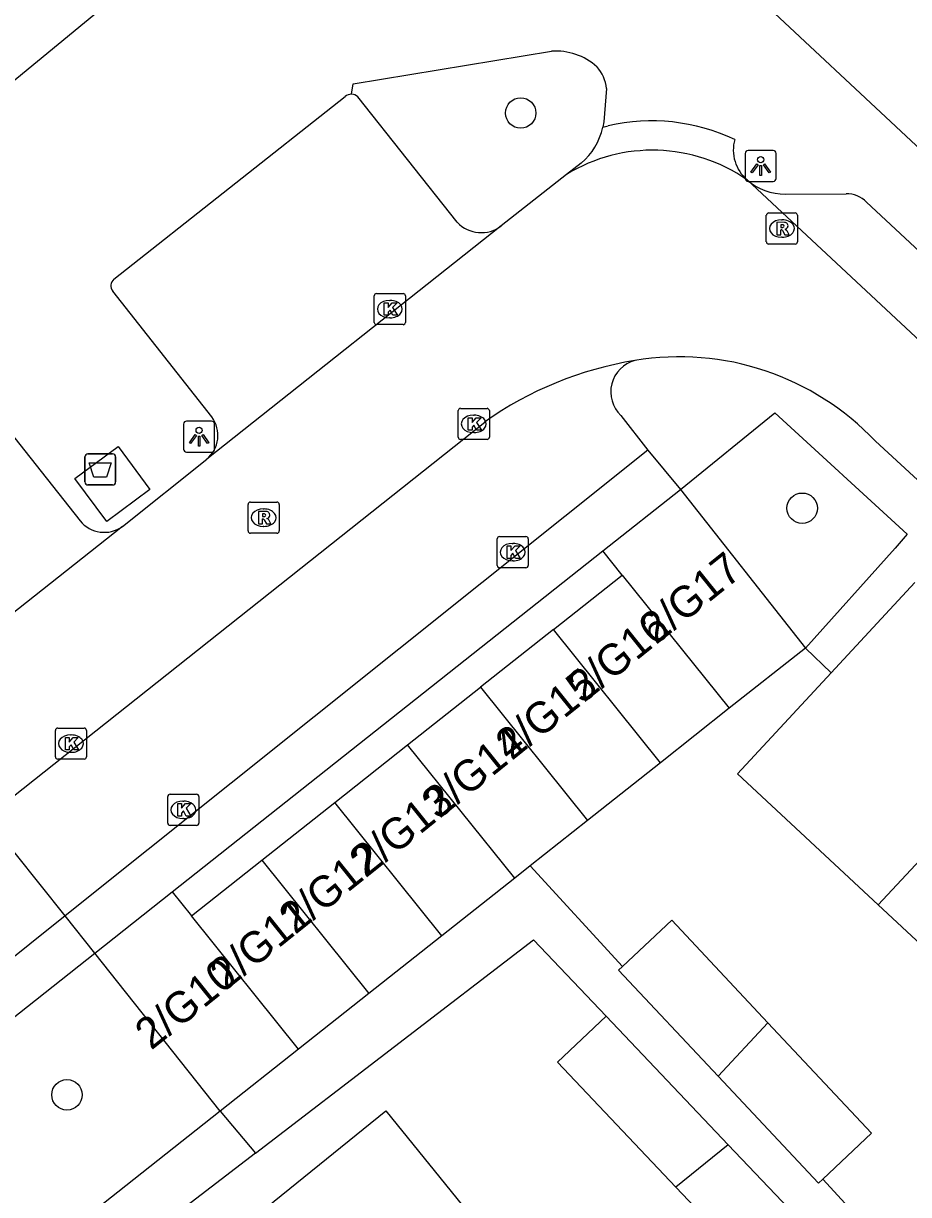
# Model space of a CAD drawing. Extents: x 162347 to 162868, y 381221 to 381813.
# Drawn here: x 162519.02 to 162547.46, y 381682.17 to 381719.8 of the extents above; entities that cross this region are included whole.
import ezdxf

# ---------------------------------------------------------------- set-up
doc = ezdxf.new("R2010")
doc.units = 0
for name, color, linetype in [('IMGEO_Afval_apart_plaats', 7, 'Continuous'), ('IMGEO_Boom', 7, 'Continuous'), ('IMGEO_Kolk', 7, 'Continuous'), ('IMGEO_Lichtpunt', 7, 'Continuous'), ('IMGEO_Pand', 7, 'Continuous'), ('IMGEO_Pand_nummerreeks', 7, 'Continuous'), ('IMGEO_Parkeervlak_open', 7, 'Continuous'), ('IMGEO_Rijbaan_lokaal_open', 7, 'Continuous'), ('IMGEO_Rioolput', 7, 'Continuous'), ('IMGEO_Voetpad_gesloten', 7, 'Continuous'), ('IMGEO_Voetpad_open', 7, 'Continuous')]:
    doc.layers.add(name, color=color, linetype=linetype)

msp = doc.modelspace()

# ---------------------------------------------------------------- linework, layer by layer
at = {"layer": 'IMGEO_Afval_apart_plaats'}
for p, q in [((162520.994, 381705.07), (162520.994, 381705.87)), ((162520.994, 381705.87), (162520.994, 381705.07)), ((162521.094, 381705.97), (162521.884, 381705.97)), ((162521.884, 381705.97), (162521.094, 381705.97)), ((162521.984, 381705.87), (162521.984, 381705.07)), ((162521.984, 381705.07), (162521.984, 381705.87)), ((162521.884, 381704.97), (162521.094, 381704.97)), ((162521.094, 381704.97), (162521.884, 381704.97))]:
    msp.add_line(p, q, dxfattribs=at)
msp.add_lwpolyline([(162521.137, 381705.684), (162521.841, 381705.684), (162521.692, 381705.214), (162521.286, 381705.214), (162521.137, 381705.684)], dxfattribs=at)
for centre, start, end in [((162521.094, 381705.87), 90, 180), ((162521.094, 381705.87), 90, 180), ((162521.884, 381705.87), 0, 90), ((162521.884, 381705.87), 360, 90), ((162521.094, 381705.07), 180, 270), ((162521.094, 381705.07), 180, 270), ((162521.884, 381705.07), 270, 0), ((162521.884, 381705.07), 270, 0)]:
    msp.add_arc(centre, 0.1, start, end, dxfattribs=at)
at = {"layer": 'IMGEO_Boom'}
for centre in [(162535, 381716.921), (162544.045, 381704.221), (162520.419, 381685.371)]:
    msp.add_circle(centre, 0.489, dxfattribs=at)
at = {"layer": 'IMGEO_Kolk'}
for p, q in [((162530.293, 381710.194), (162530.293, 381711.046)), ((162530.368, 381711.12), (162531.22, 381711.12)), ((162530.781, 381710.9), (162530.806, 381710.9)), ((162531.294, 381711.046), (162531.294, 381710.194)), ((162530.804, 381710.34), (162530.779, 381710.34)), ((162531.22, 381710.12), (162530.368, 381710.12)), ((162532.991, 381706.505), (162532.991, 381707.357)), ((162533.066, 381707.431), (162533.918, 381707.431)), ((162533.479, 381707.211), (162533.504, 381707.211)), ((162533.992, 381707.357), (162533.992, 381706.505)), ((162533.918, 381706.431), (162533.066, 381706.431)), ((162533.502, 381706.651), (162533.477, 381706.651)), ((162534.243, 381702.384), (162534.243, 381703.236)), ((162534.318, 381703.31), (162535.17, 381703.31)), ((162534.731, 381703.09), (162534.756, 381703.09)), ((162535.244, 381703.236), (162535.244, 381702.384)), ((162535.17, 381702.31), (162534.318, 381702.31)), ((162534.754, 381702.53), (162534.729, 381702.53)), ((162520.046, 381696.231), (162520.046, 381697.083)), ((162520.121, 381697.157), (162520.973, 381697.157)), ((162521.047, 381697.083), (162521.047, 381696.231)), ((162520.534, 381696.937), (162520.559, 381696.937)), ((162520.557, 381696.377), (162520.532, 381696.377)), ((162520.973, 381696.157), (162520.121, 381696.157)), ((162523.658, 381694.103), (162523.658, 381694.955)), ((162523.733, 381695.029), (162524.585, 381695.029)), ((162524.146, 381694.809), (162524.171, 381694.809)), ((162524.659, 381694.955), (162524.659, 381694.103)), ((162524.585, 381694.029), (162523.733, 381694.029)), ((162524.169, 381694.249), (162524.144, 381694.249))]:
    msp.add_line(p, q, dxfattribs=at)
for points in [[(162530.293, 381710.194), (162530.293, 381711.046)], [(162530.368, 381711.12), (162531.22, 381711.12)], [(162531.294, 381711.046), (162531.294, 381710.194)], [(162530.614, 381710.82), (162530.737, 381710.82), (162530.737, 381710.669), (162530.867, 381710.82), (162531.031, 381710.82), (162530.885, 381710.669), (162531.038, 381710.42), (162530.886, 381710.42), (162530.801, 381710.584), (162530.737, 381710.517), (162530.737, 381710.42), (162530.614, 381710.42), (162530.614, 381710.82)], [(162531.22, 381710.12), (162530.368, 381710.12)], [(162532.991, 381706.505), (162532.991, 381707.357)], [(162533.066, 381707.431), (162533.918, 381707.431)], [(162533.312, 381707.131), (162533.435, 381707.131), (162533.435, 381706.98), (162533.565, 381707.131), (162533.729, 381707.131), (162533.583, 381706.98), (162533.736, 381706.731), (162533.584, 381706.731), (162533.499, 381706.895), (162533.435, 381706.828), (162533.435, 381706.731), (162533.312, 381706.731), (162533.312, 381707.131)], [(162533.992, 381707.357), (162533.992, 381706.505)], [(162533.918, 381706.431), (162533.066, 381706.431)], [(162534.243, 381702.384), (162534.243, 381703.236)], [(162534.318, 381703.31), (162535.17, 381703.31)], [(162534.564, 381703.01), (162534.687, 381703.01), (162534.687, 381702.859), (162534.817, 381703.01), (162534.981, 381703.01), (162534.835, 381702.859), (162534.988, 381702.61), (162534.836, 381702.61), (162534.751, 381702.774), (162534.687, 381702.707), (162534.687, 381702.61), (162534.564, 381702.61), (162534.564, 381703.01)], [(162535.244, 381703.236), (162535.244, 381702.384)], [(162535.17, 381702.31), (162534.318, 381702.31)], [(162520.046, 381696.231), (162520.046, 381697.083)], [(162520.121, 381697.157), (162520.973, 381697.157)], [(162521.047, 381697.083), (162521.047, 381696.231)], [(162520.367, 381696.857), (162520.49, 381696.857), (162520.49, 381696.706), (162520.62, 381696.857), (162520.784, 381696.857), (162520.638, 381696.706), (162520.791, 381696.457), (162520.639, 381696.457), (162520.554, 381696.621), (162520.49, 381696.554), (162520.49, 381696.457), (162520.367, 381696.457), (162520.367, 381696.857)], [(162520.973, 381696.157), (162520.121, 381696.157)], [(162523.658, 381694.103), (162523.658, 381694.955)], [(162523.733, 381695.029), (162524.585, 381695.029)], [(162523.979, 381694.729), (162524.102, 381694.729), (162524.102, 381694.578), (162524.232, 381694.729), (162524.396, 381694.729), (162524.25, 381694.578), (162524.403, 381694.329), (162524.251, 381694.329), (162524.166, 381694.493), (162524.102, 381694.426), (162524.102, 381694.329), (162523.979, 381694.329), (162523.979, 381694.729)], [(162524.659, 381694.955), (162524.659, 381694.103)], [(162524.585, 381694.029), (162523.733, 381694.029)]]:
    msp.add_lwpolyline(points, dxfattribs=at)
for centre, start, end in [((162530.37, 381711.044), 91.552, 178.448), ((162530.37, 381711.044), 91.552, 178.448), ((162531.218, 381711.044), 1.552, 88.448), ((162531.218, 381711.044), 1.552, 88.448), ((162530.37, 381710.196), 181.552, 268.448), ((162530.37, 381710.196), 181.552, 268.448), ((162531.218, 381710.196), 271.552, 358.448), ((162531.218, 381710.196), 271.552, 358.448), ((162533.068, 381707.355), 91.552, 178.448), ((162533.068, 381707.355), 91.552, 178.448), ((162533.916, 381707.355), 1.552, 88.448), ((162533.916, 381707.355), 1.552, 88.448), ((162533.068, 381706.507), 181.552, 268.448), ((162533.068, 381706.507), 181.552, 268.448), ((162533.916, 381706.507), 271.552, 358.448), ((162533.916, 381706.507), 271.552, 358.448), ((162534.32, 381703.234), 91.552, 178.448), ((162534.32, 381703.234), 91.552, 178.448), ((162535.168, 381703.234), 1.552, 88.448), ((162535.168, 381703.234), 1.552, 88.448), ((162534.32, 381702.386), 181.552, 268.448), ((162534.32, 381702.386), 181.552, 268.448), ((162535.168, 381702.386), 271.552, 358.448), ((162535.168, 381702.386), 271.552, 358.448), ((162520.123, 381697.081), 91.552, 178.448), ((162520.123, 381697.081), 91.552, 178.448), ((162520.971, 381697.081), 1.552, 88.448), ((162520.971, 381697.081), 1.552, 88.448), ((162520.123, 381696.233), 181.552, 268.448), ((162520.123, 381696.233), 181.552, 268.448), ((162520.971, 381696.233), 271.552, 358.448), ((162520.971, 381696.233), 271.552, 358.448), ((162523.735, 381694.953), 91.552, 178.448), ((162523.735, 381694.953), 91.552, 178.448), ((162524.583, 381694.953), 1.552, 88.448), ((162524.583, 381694.953), 1.552, 88.448), ((162523.735, 381694.105), 181.552, 268.448), ((162523.735, 381694.105), 181.552, 268.448), ((162524.583, 381694.105), 271.552, 358.448), ((162524.583, 381694.105), 271.552, 358.448)]:
    msp.add_arc(centre, 0.0765, start, end, dxfattribs=at)
for centre, major_axis, ratio, start_param, end_param in [((162530.78, 381710.62), (-0.387, 0.002), 0.722429, 4.712389, 7.853982), ((162530.805, 381710.62), (-0.39, 0.002), 0.717154, 1.570796, 4.712389), ((162533.478, 381706.931), (-0.387, 0.002), 0.722429, 4.712389, 7.853982), ((162533.503, 381706.931), (-0.39, 0.002), 0.717154, 1.570796, 4.712389), ((162534.73, 381702.81), (-0.387, 0.002), 0.722429, 4.712389, 7.853982), ((162534.755, 381702.81), (-0.39, 0.002), 0.717154, 1.570796, 4.712389), ((162520.533, 381696.657), (-0.387, 0.002), 0.722429, 4.712389, 7.853982), ((162520.558, 381696.657), (-0.39, 0.002), 0.717154, 1.570796, 4.712389), ((162524.145, 381694.529), (-0.387, 0.002), 0.722429, 4.712389, 7.853982), ((162524.17, 381694.529), (-0.39, 0.002), 0.717154, 1.570796, 4.712389)]:
    msp.add_ellipse(centre, major_axis=major_axis, ratio=ratio, start_param=start_param, end_param=end_param, dxfattribs=at)
at = {"layer": 'IMGEO_Lichtpunt'}
for p, q in [((162542.213, 381715.623), (162542.213, 381714.816)), ((162542.213, 381715.623), (162542.213, 381714.816)), ((162543.115, 381715.718), (162542.307, 381715.718)), ((162543.115, 381715.718), (162542.307, 381715.718)), ((162543.209, 381714.816), (162543.209, 381715.623)), ((162543.209, 381714.816), (162543.209, 381715.623)), ((162542.307, 381714.722), (162543.115, 381714.722)), ((162542.307, 381714.722), (162543.115, 381714.722)), ((162524.167, 381706.926), (162524.167, 381706.119)), ((162524.167, 381706.926), (162524.167, 381706.119)), ((162525.069, 381707.021), (162524.261, 381707.021)), ((162525.069, 381707.021), (162524.261, 381707.021)), ((162525.163, 381706.119), (162525.163, 381706.926)), ((162525.163, 381706.119), (162525.163, 381706.926)), ((162524.261, 381706.025), (162525.069, 381706.025)), ((162524.261, 381706.025), (162525.069, 381706.025))]:
    msp.add_line(p, q, dxfattribs=at)
for points in [[(162542.587, 381715.287), (162542.626, 381715.259), (162542.438, 381714.997), (162542.4, 381715.024), (162542.587, 381715.287)], [(162542.689, 381715.239), (162542.736, 381715.239), (162542.736, 381714.917), (162542.689, 381714.917), (162542.689, 381715.239)], [(162542.799, 381715.259), (162542.837, 381715.286), (162543.024, 381715.024), (162542.985, 381714.996), (162542.799, 381715.259)], [(162524.541, 381706.59), (162524.58, 381706.562), (162524.392, 381706.3), (162524.354, 381706.327), (162524.541, 381706.59)], [(162524.643, 381706.542), (162524.69, 381706.542), (162524.69, 381706.22), (162524.643, 381706.22), (162524.643, 381706.542)], [(162524.753, 381706.562), (162524.791, 381706.589), (162524.978, 381706.327), (162524.939, 381706.299), (162524.753, 381706.562)]]:
    msp.add_lwpolyline(points, dxfattribs=at)
for centre in [(162542.712, 381715.421), (162524.666, 381706.724)]:
    msp.add_circle(centre, 0.0994, dxfattribs=at)
for centre, start, end in [((162542.307, 381715.623), 90, 180), ((162542.307, 381715.623), 90, 180), ((162543.115, 381715.623), 0, 90), ((162543.115, 381715.623), 0, 90), ((162542.307, 381714.816), 180, 270), ((162542.307, 381714.816), 180, 270), ((162543.115, 381714.816), 270, 0), ((162543.115, 381714.816), 270, 360), ((162524.261, 381706.926), 90, 180), ((162524.261, 381706.926), 90, 180), ((162525.069, 381706.926), 0, 90), ((162525.069, 381706.926), 0, 90), ((162524.261, 381706.119), 180, 270), ((162524.261, 381706.119), 180, 270), ((162525.069, 381706.119), 270, 0), ((162525.069, 381706.119), 270, 360)]:
    msp.add_arc(centre, 0.0946, start, end, dxfattribs=at)
at = {"layer": 'IMGEO_Pand'}
for points in [[(162518.63, 381717.886), (162525.696, 381723.717)], [(162537.642, 381702.856), (162540.132, 381704.823)], [(162540.132, 381704.823), (162544.148, 381699.726)], [(162538.262, 381702.071), (162537.642, 381702.856)], [(162536.051, 381700.322), (162538.262, 381702.071)], [(162538.262, 381702.071), (162541.703, 381697.791)], [(162544.973, 381698.927), (162547.662, 381701.832)], [(162536.051, 381700.322), (162533.709, 381698.468)], [(162539.492, 381696.043), (162536.051, 381700.322)], [(162544.148, 381699.726), (162541.703, 381697.791)], [(162546.49, 381691.473), (162541.97, 381695.681), (162544.973, 381698.927)], [(162531.366, 381696.615), (162533.709, 381698.468)], [(162533.709, 381698.468), (162537.149, 381694.189)], [(162541.703, 381697.791), (162539.492, 381696.043)], [(162552.208, 381697.599), (162546.49, 381691.473)], [(162529.023, 381694.761), (162531.366, 381696.615)], [(162534.807, 381692.336), (162531.366, 381696.615)], [(162539.492, 381696.043), (162537.149, 381694.189)], [(162526.68, 381692.908), (162529.023, 381694.761)], [(162532.464, 381690.482), (162529.023, 381694.761)], [(162537.149, 381694.189), (162535.306, 381692.731)], [(162524.422, 381691.121), (162526.68, 381692.908)], [(162526.68, 381692.908), (162530.121, 381688.629)], [(162535.306, 381692.731), (162534.807, 381692.336)], [(162534.807, 381692.336), (162532.464, 381690.482)], [(162521.312, 381689.925), (162523.799, 381691.897)], [(162523.799, 381691.897), (162524.422, 381691.121)], [(162550.927, 381687.341), (162546.49, 381691.473)], [(162527.863, 381686.842), (162524.422, 381691.121)], [(162538.276, 381689.5), (162539.852, 381690.979), (162542.943, 381687.685)], [(162532.464, 381690.482), (162530.121, 381688.629)], [(162525.341, 381684.847), (162521.312, 381689.925)], [(162541.345, 381685.973), (162538.148, 381689.38), (162538.276, 381689.5)], [(162530.121, 381688.629), (162527.863, 381686.842)], [(162539.988, 381682.409), (162536.182, 381686.418), (162537.745, 381687.902)], [(162537.745, 381687.902), (162541.669, 381683.768)], [(162542.943, 381687.685), (162541.345, 381685.973)], [(162542.943, 381687.685), (162546.276, 381684.134), (162544.711, 381682.665)], [(162527.863, 381686.842), (162525.341, 381684.847)], [(162544.711, 381682.665), (162544.572, 381682.535), (162541.345, 381685.973)], [(162527.802, 381675.205), (162524.214, 381679.638), (162530.663, 381684.862), (162535.551, 381678.822)], [(162541.669, 381683.768), (162539.988, 381682.409)], [(162541.669, 381683.768), (162544.268, 381681.031), (162544.173, 381680.942), (162544.128, 381680.899)], [(162544.128, 381680.899), (162542.705, 381679.548), (162539.988, 381682.409)]]:
    msp.add_lwpolyline(points, dxfattribs=at)
at = {"layer": 'IMGEO_Parkeervlak_open'}
for points in [[(162532.959, 381713.412), (162529.766, 381717.44)], [(162520.357, 381691.127), (162517.937, 381694.149)]]:
    msp.add_lwpolyline(points, dxfattribs=at)
for centre, radius, start, end in [((162529.556, 381717.221), 0.303, 46.2549, 87.7676), ((162533.73, 381714.127), 1.051, 222.8426, 307.9582)]:
    msp.add_arc(centre, radius, start, end, dxfattribs=at)
at = {"layer": 'IMGEO_Rijbaan_lokaal_open'}
for points in [[(162536.476, 381714.949), (162534.376, 381713.298)], [(162591.19, 381669.184), (162580.185, 381679.418), (162542.273, 381714.77)], [(162534.376, 381713.298), (162524.911, 381705.794)], [(162517.7, 381694.186), (162533.842, 381706.991)], [(162588.969, 381666.789), (162586.238, 381669.332), (162574.275, 381680.474), (162573.453, 381681.241), (162560.818, 381693.021), (162548.027, 381704.879), (162546.399, 381706.372)], [(162522.199, 381703.639), (162524.911, 381705.794)], [(162522.199, 381703.639), (162499.727, 381685.849)]]:
    msp.add_lwpolyline(points, dxfattribs=at)
for centre, radius, start, end in [((162539.238, 381710.429), 5.297, 55.0401, 121.4226), ((162540.102, 381700.426), 8.661, 43.354, 99.5139), ((162540.529, 381697.545), 11.574, 99.2428, 125.2941)]:
    msp.add_arc(centre, radius, start, end, dxfattribs=at)
at = {"layer": 'IMGEO_Rioolput'}
for p, q in [((162542.893, 381712.782), (162542.893, 381713.634)), ((162542.968, 381713.708), (162543.82, 381713.708)), ((162543.894, 381713.634), (162543.894, 381712.782)), ((162543.381, 381713.488), (162543.406, 381713.488)), ((162543.404, 381712.928), (162543.379, 381712.928)), ((162543.82, 381712.708), (162542.968, 381712.708)), ((162526.238, 381703.492), (162526.238, 381704.344)), ((162526.313, 381704.418), (162527.165, 381704.418)), ((162526.726, 381704.198), (162526.751, 381704.198)), ((162527.239, 381704.344), (162527.239, 381703.492)), ((162527.165, 381703.418), (162526.313, 381703.418)), ((162526.749, 381703.638), (162526.724, 381703.638))]:
    msp.add_line(p, q, dxfattribs=at)
for points in [[(162542.893, 381712.782), (162542.893, 381713.634)], [(162542.968, 381713.708), (162543.82, 381713.708)], [(162543.894, 381713.634), (162543.894, 381712.782)], [(162543.482, 381713.406), (162543.23, 381713.408), (162543.23, 381713.008)], [(162543.23, 381713.008), (162543.354, 381713.008), (162543.354, 381713.17), (162543.365, 381713.17)], [(162543.408, 381713.327), (162543.354, 381713.327), (162543.354, 381713.246)], [(162543.354, 381713.246), (162543.406, 381713.246)], [(162543.412, 381713.141), (162543.483, 381713.008), (162543.623, 381713.008), (162543.558, 381713.134)], [(162543.82, 381712.708), (162542.968, 381712.708)], [(162526.238, 381703.492), (162526.238, 381704.344)], [(162526.313, 381704.418), (162527.165, 381704.418)], [(162526.827, 381704.116), (162526.575, 381704.118), (162526.575, 381703.718)], [(162527.239, 381704.344), (162527.239, 381703.492)], [(162526.575, 381703.718), (162526.699, 381703.718), (162526.699, 381703.88), (162526.71, 381703.88)], [(162526.753, 381704.037), (162526.699, 381704.037), (162526.699, 381703.956)], [(162526.699, 381703.956), (162526.751, 381703.956)], [(162526.757, 381703.851), (162526.828, 381703.718), (162526.968, 381703.718), (162526.903, 381703.844)], [(162527.165, 381703.418), (162526.313, 381703.418)]]:
    msp.add_lwpolyline(points, dxfattribs=at)
for centre, radius, start, end in [((162542.97, 381713.632), 0.0765, 91.552, 178.448), ((162542.97, 381713.632), 0.0765, 91.552, 178.448), ((162543.818, 381713.632), 0.0765, 1.552, 88.448), ((162543.818, 381713.632), 0.0765, 1.552, 88.448), ((162543.364, 381713.117), 0.0533, 26.0293, 88.6989), ((162543.39, 381713.435), 0.19, 274.7715, 282.9687), ((162543.414, 381713.231), 0.0964, 77.0061, 93.1865), ((162543.428, 381713.288), 0.0378, 276.6634, 79.6772), ((162543.481, 381713.296), 0.109, 350.3612, 89.416), ((162543.479, 381713.296), 0.112, 277.5842, 350.9817), ((162543.463, 381713.081), 0.108, 29.5134, 73.7905), ((162542.97, 381712.784), 0.0765, 181.552, 268.448), ((162542.97, 381712.784), 0.0765, 181.552, 268.448), ((162543.818, 381712.784), 0.0765, 271.552, 358.448), ((162543.818, 381712.784), 0.0765, 271.552, 358.448), ((162526.315, 381704.342), 0.0765, 91.552, 178.448), ((162526.315, 381704.342), 0.0765, 91.552, 178.448), ((162526.826, 381704.006), 0.109, 350.3612, 89.416), ((162527.163, 381704.342), 0.0765, 1.552, 88.448), ((162527.163, 381704.342), 0.0765, 1.552, 88.448), ((162526.709, 381703.827), 0.0533, 26.0293, 88.6989), ((162526.735, 381704.145), 0.19, 274.7715, 282.9687), ((162526.759, 381703.941), 0.0964, 77.0061, 93.1865), ((162526.773, 381703.998), 0.0378, 276.6634, 79.6772), ((162526.824, 381704.006), 0.112, 277.5842, 350.9817), ((162526.808, 381703.791), 0.108, 29.5134, 73.7905), ((162526.315, 381703.494), 0.0765, 181.552, 268.448), ((162526.315, 381703.494), 0.0765, 181.552, 268.448), ((162527.163, 381703.494), 0.0765, 271.552, 358.448), ((162527.163, 381703.494), 0.0765, 271.552, 358.448)]:
    msp.add_arc(centre, radius, start, end, dxfattribs=at)
for centre, major_axis, ratio, start_param, end_param in [((162543.38, 381713.208), (-0.387, 0.002), 0.722429, 4.712389, 7.853982), ((162543.405, 381713.208), (-0.39, 0.002), 0.717154, 1.570796, 4.712389), ((162526.725, 381703.918), (-0.387, 0.002), 0.722429, 4.712389, 7.853982), ((162526.75, 381703.918), (-0.39, 0.002), 0.717154, 1.570796, 4.712389)]:
    msp.add_ellipse(centre, major_axis=major_axis, ratio=ratio, start_param=start_param, end_param=end_param, dxfattribs=at)
at = {"layer": 'IMGEO_Voetpad_gesloten'}
msp.add_lwpolyline([(162522.061, 381706.201), (162523.083, 381704.821), (162521.704, 381703.796), (162520.67, 381705.179), (162522.061, 381706.201)], dxfattribs=at)
at = {"layer": 'IMGEO_Voetpad_open'}
for points in [[(162544.927, 381722.323), (162542.992, 381720.281), (162563.297, 381701.321)], [(162529.568, 381717.524), (162529.615, 381717.858), (162535.987, 381718.904)], [(162537.757, 381717.705), (162537.667, 381716.641), (162537.637, 381716.462)], [(162521.93, 381711.58), (162529.359, 381717.448)], [(162537.637, 381716.462), (162537.815, 381716.509)], [(162536.94, 381715.31), (162536.476, 381714.949)], [(162543.509, 381714.316), (162545.457, 381714.327)], [(162546.116, 381714.053), (162581.635, 381680.986), (162619.498, 381645.735), (162631.092, 381634.929), (162631.144, 381634.866)], [(162525.076, 381707.153), (162521.89, 381711.192)], [(162517.644, 381707.854), (162520.842, 381703.818)], [(162538.222, 381707.201), (162539.084, 381706.089)], [(162540.132, 381704.823), (162543.164, 381707.283), (162547.422, 381703.385), (162547.035, 381702.94), (162544.148, 381699.726)], [(162539.084, 381706.089), (162520.357, 381691.127)], [(162539.084, 381706.089), (162540.132, 381704.823)], [(162523.799, 381691.897), (162537.642, 381702.856)], [(162544.973, 381698.927), (162544.148, 381699.726)], [(162538.276, 381689.5), (162535.306, 381692.731)], [(162520.357, 381691.127), (162514.723, 381686.61), (162513.016, 381688.643)], [(162521.312, 381689.925), (162520.357, 381691.127)], [(162526.479, 381683.499), (162535.416, 381690.356), (162537.745, 381687.902)], [(162525.341, 381684.847), (162520.82, 381681.267), (162519.71, 381680.397), (162515.643, 381685.433), (162521.312, 381689.925)], [(162525.341, 381684.847), (162526.479, 381683.499)], [(162526.479, 381683.499), (162520.914, 381679.229), (162577.5, 381609.273), (162579.694, 381611.087)], [(162546.747, 381680.449), (162544.711, 381682.665)]]:
    msp.add_lwpolyline(points, dxfattribs=at)
for centre, radius, start, end in [((162536.131, 381716.917), 1.992, 48.5378, 94.1464), ((162536.467, 381717.563), 1.298, 6.2969, 40.7656), ((162529.559, 381717.224), 0.3, 88.2365, 131.7297), ((162539.217, 381710.413), 6.255, 64.8465, 102.9534), ((162535.642, 381716.882), 2.038, 309.5387, 348.1105), ((162543.12, 381715.74), 1.288, 164.9425, 228.8986), ((162543.494, 381716.184), 1.868, 229.1905, 270.4715), ((162545.456, 381713.395), 0.932, 44.9144, 89.9323), ((162522.107, 381711.366), 0.278, 129.621, 218.607), ((162538.936, 381707.96), 1.042, 104.7779, 226.7685), ((162524.271, 381706.561), 0.999, 309.8179, 36.3369), ((162521.613, 381704.432), 0.986, 218.5184, 306.4528)]:
    msp.add_arc(centre, radius, start, end, dxfattribs=at)

# ---------------------------------------------------------------- texts
at = {"layer": 'IMGEO_Pand_nummerreeks'}
for s, p in [('2/G17', (162539.346, 381699.817)), ('2/G16', (162537.029, 381697.955)), ('2/G15', (162534.711, 381696.093)), ('2/G14', (162532.393, 381694.231)), ('2/G13', (162530.076, 381692.369)), ('2/G12', (162527.753, 381690.503)), ('2/G11', (162525.526, 381688.714)), ('2/G10', (162523.125, 381686.785))]:
    msp.add_text(s, height=1, rotation=38.7778, dxfattribs=at).set_placement(p)

doc.saveas('drawing.dxf')
